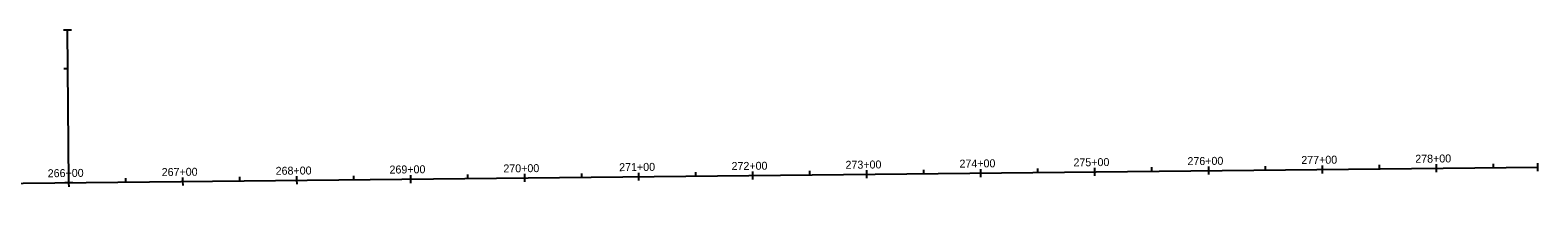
# Model space of a CAD drawing. Extents: x 596008 to 607538, y 326212 to 405053.
# Drawn here: x 603294 to 604617, y 387623 to 387771 of the extents above; entities that cross this region are included whole.
import ezdxf

# ---------------------------------------------------------------- set-up
doc = ezdxf.new("R2010")
doc.units = 0
doc.layers.add('P_ALI_200', color=7, linetype='Continuous')
doc.layers.add('P_ALI_200_Sta', color=7, linetype='Continuous')

msp = doc.modelspace()

# ---------------------------------------------------------------- linework, layer by layer
at = {"layer": 'P_ALI_200'}
for points in [[(603327.9, 387637.3), (603326.5, 387771.2)], [(601986.3, 387623.1), (604616.7, 387650.9)]]:
    msp.add_lwpolyline(points, dxfattribs=at)
at = {"layer": 'P_ALI_200_Sta'}
for points in [[(603326.5, 387771.2), (603323, 387771.1)], [(603326.5, 387771.2), (603326.5, 387771.2)], [(603330, 387771.2), (603326.5, 387771.2)], [(603326.9, 387737.3), (603323.4, 387737.2)], [(604377.9, 387648.4), (604377.9, 387651.9)], [(604427.9, 387648.9), (604427.9, 387652.4)], [(604477.9, 387649.4), (604477.8, 387652.9)], [(604527.9, 387650), (604527.8, 387653.5)], [(604577.9, 387650.5), (604577.8, 387654)], [(604616.7, 387650.9), (604616.6, 387654.4)], [(603327.9, 387637.3), (603327.9, 387640.8)], [(603377.9, 387637.8), (603377.9, 387641.3)], [(603427.9, 387638.3), (603427.9, 387641.8)], [(603427.9, 387638.3), (603427.9, 387638.3)], [(603428, 387634.8), (603427.9, 387638.3)], [(603477.9, 387638.9), (603477.9, 387642.4)], [(603527.9, 387639.4), (603527.9, 387642.9)], [(603527.9, 387639.4), (603527.9, 387639.4)], [(603528, 387635.9), (603527.9, 387639.4)], [(603577.9, 387639.9), (603577.9, 387643.4)], [(603627.9, 387640.5), (603627.9, 387644)], [(603627.9, 387640.5), (603627.9, 387640.5)], [(603628, 387637), (603627.9, 387640.5)], [(603677.9, 387641), (603677.9, 387644.5)], [(603727.9, 387641.5), (603727.9, 387645)], [(603727.9, 387641.5), (603727.9, 387641.5)], [(603728, 387638), (603727.9, 387641.5)], [(603777.9, 387642), (603777.9, 387645.5)], [(603827.9, 387642.6), (603827.9, 387646.1)], [(603827.9, 387642.6), (603827.9, 387642.6)], [(603828, 387639.1), (603827.9, 387642.6)], [(603877.9, 387643.1), (603877.9, 387646.6)], [(603927.9, 387643.6), (603927.9, 387647.1)], [(603927.9, 387643.6), (603927.9, 387643.6)], [(603928, 387640.1), (603927.9, 387643.6)], [(603977.9, 387644.2), (603977.9, 387647.7)], [(604027.9, 387644.7), (604027.9, 387648.2)], [(604027.9, 387644.7), (604027.9, 387644.7)], [(604027.9, 387641.2), (604027.9, 387644.7)], [(604077.9, 387645.2), (604077.9, 387648.7)], [(604127.9, 387645.7), (604127.9, 387649.2)], [(604127.9, 387645.7), (604127.9, 387645.7)], [(604127.9, 387642.2), (604127.9, 387645.7)], [(604177.9, 387646.3), (604177.9, 387649.8)], [(604227.9, 387646.8), (604227.9, 387650.3)], [(604227.9, 387646.8), (604227.9, 387646.8)], [(604227.9, 387643.3), (604227.9, 387646.8)], [(604277.9, 387647.3), (604277.9, 387650.8)], [(604327.9, 387647.9), (604327.9, 387651.4)], [(604327.9, 387647.9), (604327.9, 387647.9)], [(604327.9, 387644.4), (604327.9, 387647.9)], [(604427.9, 387648.9), (604427.9, 387648.9)], [(604427.9, 387645.4), (604427.9, 387648.9)], [(604527.9, 387650), (604527.9, 387650)], [(604527.9, 387646.5), (604527.9, 387650)], [(604616.7, 387650.9), (604616.7, 387650.9)], [(604616.7, 387647.4), (604616.7, 387650.9)], [(603327.9, 387637.3), (603324.4, 387637.3)], [(603327.9, 387637.3), (603327.9, 387637.3)], [(603328, 387633.8), (603327.9, 387637.3)], [(603327.9, 387637.3), (603327.9, 387637.3)], [(603331.4, 387637.3), (603327.9, 387637.3)]]:
    msp.add_lwpolyline(points, dxfattribs=at)

# ---------------------------------------------------------------- texts
for s, height, rotation, p in [('1', 0.0000000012, 90.6087, (603321.5, 387771.1)), ('268+00', 7, 0.6053, (603509.3, 387644.2)), ('269+00', 7, 0.6053, (603609.2, 387645.3)), ('270+00', 7, 0.6053, (603709.1, 387646.3)), ('271+00', 7, 0.6053, (603810.7, 387647.4)), ('272+00', 7, 0.6053, (603909.3, 387648.4)), ('273+00', 7, 0.6053, (604009.3, 387649.5)), ('274+00', 7, 0.6053, (604109.3, 387650.5)), ('275+00', 7, 0.6053, (604209.3, 387651.6)), ('276+00', 7, 0.6053, (604309.3, 387652.7)), ('277+00', 7, 0.6053, (604409.2, 387653.7)), ('278+00', 7, 0.6053, (604509.2, 387654.8)), ('278+89', 0.0000000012, 0.6053, (604616.6, 387655.9)), ('266+00', 7, 0.6053, (603309.3, 387642.1)), ('267+00', 7, 0.6053, (603409.3, 387643.1)), ('0', 0.0000000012, 90.6087, (603322.9, 387637.2))]:
    msp.add_text(s, height=height, rotation=rotation, dxfattribs=at).set_placement(p)

doc.saveas('drawing.dxf')
